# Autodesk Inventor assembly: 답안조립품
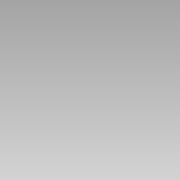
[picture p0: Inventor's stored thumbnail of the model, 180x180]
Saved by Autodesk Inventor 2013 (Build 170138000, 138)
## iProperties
Created: 2017-02
Part Number: 답안조립품
Document SubType Name: Assembly
Designer: hana-cad19
Author: hana-cad19
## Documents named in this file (1)
- C:\Documents and Settings\hana-cad19\바탕 화면\470208V1017\답안조립품.iam
